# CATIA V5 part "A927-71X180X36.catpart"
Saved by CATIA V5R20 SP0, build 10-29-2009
Part number: A927-71X180X36
Source: Unknown
Property "A": "36.000"
Property "ARTICLENO": "A927-71X180X36"
Property "BOMINFO": "A927-71X180X36"
Property "CODE": "A927-71X180X36"
Property "CREATOR": "CADENAS GmbH"
Property "D": "14.000"
Property "D1": "20.000"
Property "F": "18.000"
Property "FORM": "A"
Property "L": "180.000"
Property "L1": "90.000"
Property "L2": "20.000"
Property "L3": "50.000"
Property "LINA": "A927-71X180X36"
Property "NB": "A927-71X180X36"
Property "NBSYN": "$CODE."
Property "NN": "A927"
Property "NT": "VDI 3387 Removable Die Heels, steel and self-lubricating"
Property "R": "16.000"
Property "S": "36.000"
Property "SUPPLIER": "CF"
Property "T": "16.000"
Property "W": "71.000"
Bounding box of the stored display mesh (mm): x -35.5 to 35.5, y 0 to 180, z -36 to 0
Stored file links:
  C:\Users\borellobunino\Desktop\3D X SITO CF\A927\GSB_OILLESS_G2290507118036\CATIAV5\A927-71X180X36.catpart
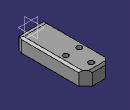
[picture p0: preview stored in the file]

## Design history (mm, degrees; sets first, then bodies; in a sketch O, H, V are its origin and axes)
Body1 "Geometry.1" (main body)
  Solid1 "A927-71X180X36.catpart": solid without history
